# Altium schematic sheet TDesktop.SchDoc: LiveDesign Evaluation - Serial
size A3; Organization: Altium Limited; Address1: L3, 12a Rodborough Rd; Address2: Frenchs Forest; Address3: NSW; Address4: Australia 2086; DocumentNumber: 5; SheetNumber: 5; SheetTotal: 7
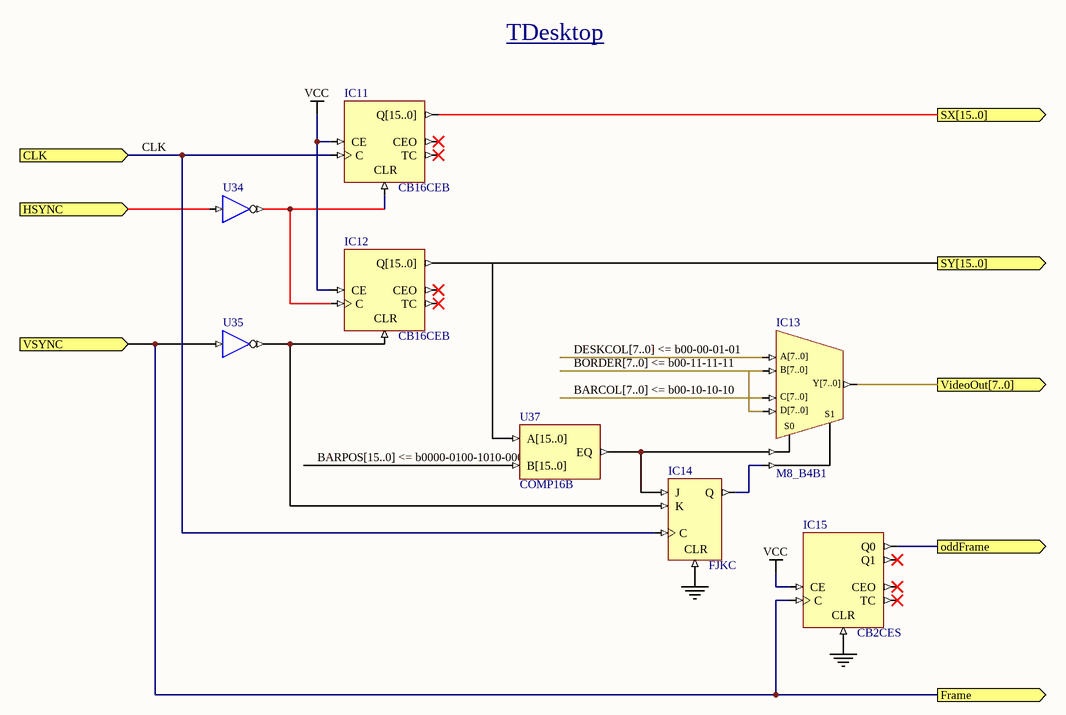
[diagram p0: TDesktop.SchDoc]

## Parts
IC11  CB16CEB
IC12  CB16CEB
IC13  M8_B4B1
IC14  FJKC
IC15  CB2CES
U34  INV  (value not drawn)
U35  BUF  (value not drawn)
U37  COMP16B

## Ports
CLK (in), Frame (out), HSYNC (in), oddFrame (out), SX[15..0] (out), SY[15..0] (out), VideoOut[7..0] (out), VSYNC (in)

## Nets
GND: IC14.CLR IC15.CLR
VCC: IC11.CE IC12.CE IC15.CE
CLK: IC11.C IC14.C ; port CLK
Frame: IC15.C U35.I ; port VSYNC, port Frame
HSYNC: U34.I ; port HSYNC
oddFrame: IC15.Q0 ; port oddFrame
NetIC11_CLR: IC11.CLR IC12.C U34.O
NetIC12_CLR: IC12.CLR IC14.K U35.O
NetIC13_S0: IC13.S0 IC14.J U37.EQ
NetIC13_S1: IC13.S1 IC14.Q

Not connected (* = marked no-connect by the designer): IC11 CEO* Q[15..0] TC*; IC12 CEO* Q[15..0] TC*; IC13 A[7..0] B[7..0] C[7..0] D[7..0] Y[7..0]; IC15 CEO* Q1* TC*; U37 A[15..0] B[15..0]

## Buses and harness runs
bus BARCOL[7..0] <= b00-10-10-10
bus BARPOS[15..0] <= b0000-0100-1010-000
bus BORDER[7..0] <= b00-11-11-11
bus DESKCOL[7..0] <= b00-00-01-01

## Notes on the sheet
- TDesktop

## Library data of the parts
IC11 IC12 = CB16CEB: 16-Bit Cascadable Binary Counters with Clock Enable and Asynchronous Clear, Bus Version; Xilinx Equivalent: CB16CE; ArchiveName: GENERIC; VHDLIB_SIM: GENERIC_LIB
IC13 = M8_B4B1: 4x8-Bit Bus to 1x8-Bit Bus Multiplexer; ArchiveName: GENERIC; VHDLIB_SIM: GENERIC_LIB
IC14 = FJKC: J-K Flip-Flop with Asynchronous Clear; ArchiveName: GENERIC; VHDLIB_SIM: GENERIC_LIB
IC15 = CB2CES: 2-Bit Cascadable Binary Counters with Clock Enable and Asynchronous Clear, Single Pin Version; Xilinx Equivalent: CB2CE; ArchiveName: GENERIC; VHDLIB_SIM: GENERIC_LIB
U34 U35 = INV: Inverter; ArchiveName: GENERIC; VHDLIB_SIM: GENERIC_LIB
U37 = COMP16B: 16-Bit Identity Comparator, Bus Version; Xilinx Equivalent: COMP16; ArchiveName: GENERIC; VHDLIB_SIM: GENERIC_LIB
